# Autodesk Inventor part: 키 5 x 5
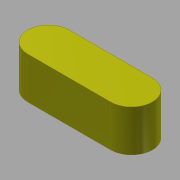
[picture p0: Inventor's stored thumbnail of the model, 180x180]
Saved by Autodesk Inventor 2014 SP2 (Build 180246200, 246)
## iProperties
Created: 2011-04
Part Number: 키 5 x 5
Document SubType Name: Modeling
Designer: pww
Density: 7.86 g/cm^3
Material: 강철, 연강
Appearance: 노란색
Author: pww
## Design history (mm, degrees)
sketch "스케치1"
  geometry: L1 (-5, -2.5)-(5, -2.5); L2 (5, 2.5)-(-5, 2.5); A1 r 2.5 centre (-5, 0) between (-5, 2.5) and (-5, -2.5); A2 r 2.5 centre (5, 0) between (5, -2.5) and (5, 2.5); 1 further point
  constraints: 4 end point, 4 point on circle, 2 centre point
extrude "돌출1" new body sketch "스케치1" distance "d0" = 5; taper "d1" = 0 deg
node "솔리드1"
